(* Logix 5000 project; controller Example_PLC vendor 1 type 14 code 77 rev 19.11; software revision 19.01; part 6 of 6 *)
(* AKD_Stop_Smooth, continued *)

ROUTINE Logic   (* ladder *)
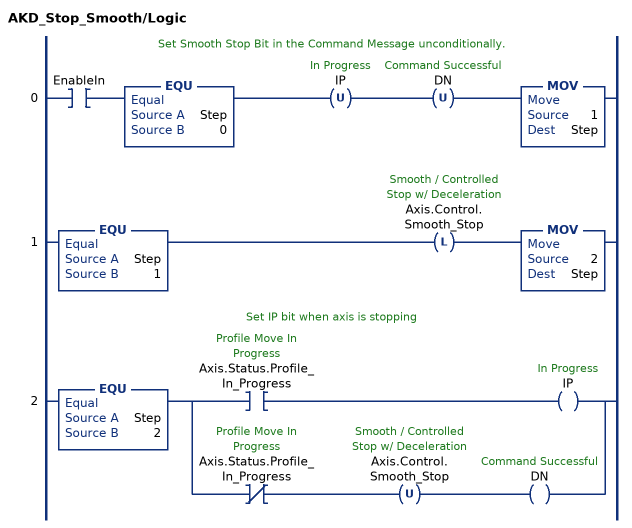
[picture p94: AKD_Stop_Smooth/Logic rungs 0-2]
   // Set Smooth Stop Bit in the Command Message unconditionally.
   0: XIC(EnableIn)EQU(Step,0)OTU(IP)OTU(DN)MOV(1,Step);
   1: EQU(Step,1)OTL(Axis.Control.Smooth_Stop)MOV(2,Step);
   // Set IP bit when axis is stopping
   2: EQU(Step,2)[XIC(Axis.Status.Profile_In_Progress) OTE(IP) ,XIO(Axis.Status.Profile_In_Progress) OTU(Axis.Control.Smooth_Stop) OTE(DN) ];
END_ROUTINE

ROUTINE Prescan   (* ladder *)
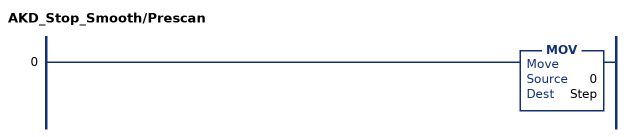
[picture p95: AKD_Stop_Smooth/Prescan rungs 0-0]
   0: MOV(0,Step);
END_ROUTINE
END_ADD_ON_INSTRUCTION

ADD_ON_INSTRUCTION AKD_Torque_Move   (* revision 2.1, ExecutePrescan, ExecuteEnableInFalse *)
// Set Torque Command
VAR_OUTPUT
   DN : BOOL; {access Read Only, visible}   // Command Successful
   ER : BOOL; {access Read Only, visible}   // Error
END_VAR
VAR_IN_OUT
   Axis : AKD_Axis; {required}
END_VAR
VAR_INPUT
   Torque : DINT; {required}   // Torque Command
END_VAR
VAR
   Response_Bytes : SINT[8];
   OS_LoadStart : BOOL;
   Command_Timeout : TIMER := (PRE := 100);   // Timeout Timer
   Command_Message_Type : SINT;   // Command Message Type
   Command_Axis_Number : SINT;   // Command Axis Number
   Response_Message_Type : SINT;   // Response Message Type
   Response_Axis_Number : SINT;   // Response Axis Number
   Command_Bytes : SINT[8];
   Step : SINT;
END_VAR

ROUTINE EnableInFalse   (* ladder *)
// EnableIn_False
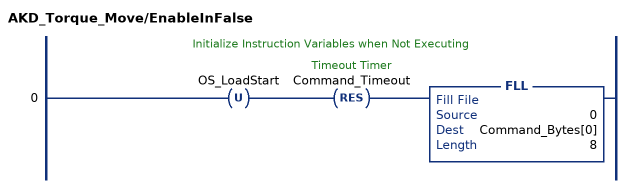
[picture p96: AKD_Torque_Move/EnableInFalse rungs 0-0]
   // Initialize Instruction Variables when Not Executing
   0: OTU(OS_LoadStart)RES(Command_Timeout)FLL(0,Command_Bytes[0],8);
END_ROUTINE

ROUTINE Logic   (* ladder *)
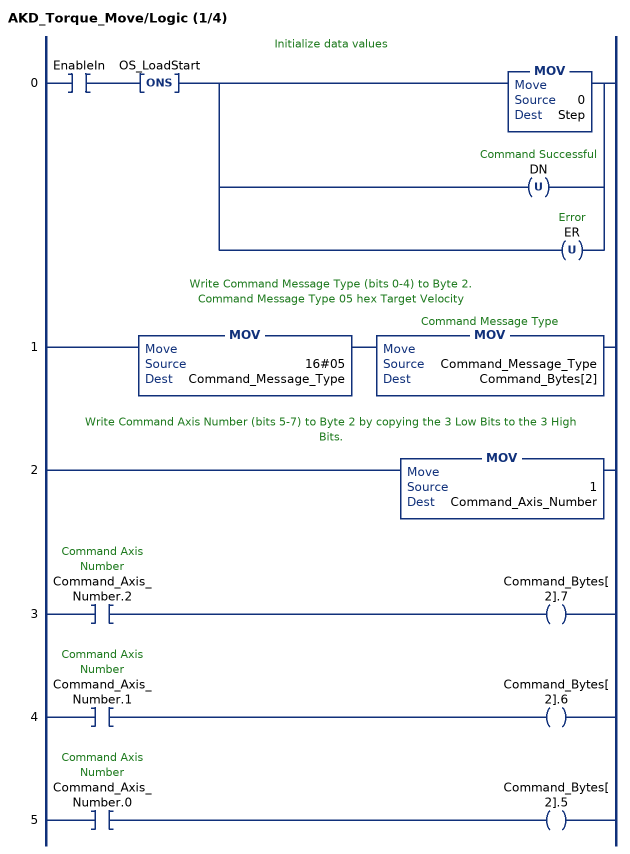
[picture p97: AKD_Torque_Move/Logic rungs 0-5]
   // Initialize data values
   0: XIC(EnableIn)ONS(OS_LoadStart)[MOV(0,Step) ,OTU(DN) ,OTU(ER) ];
   // Write Command Message Type (bits 0-4) to Byte 2.
   // Command Message Type 05 hex Target Velocity
   1: MOV(16#05,Command_Message_Type)MOV(Command_Message_Type,Command_Bytes[2]);
   // Write Command Axis Number (bits 5-7) to Byte 2 by copying the 3 Low Bits to the 3 High Bits.
   2: MOV(1,Command_Axis_Number);
   3: XIC(Command_Axis_Number.2)OTE(Command_Bytes[2].7);
   4: XIC(Command_Axis_Number.1)OTE(Command_Bytes[2].6);
   5: XIC(Command_Axis_Number.0)OTE(Command_Bytes[2].5);
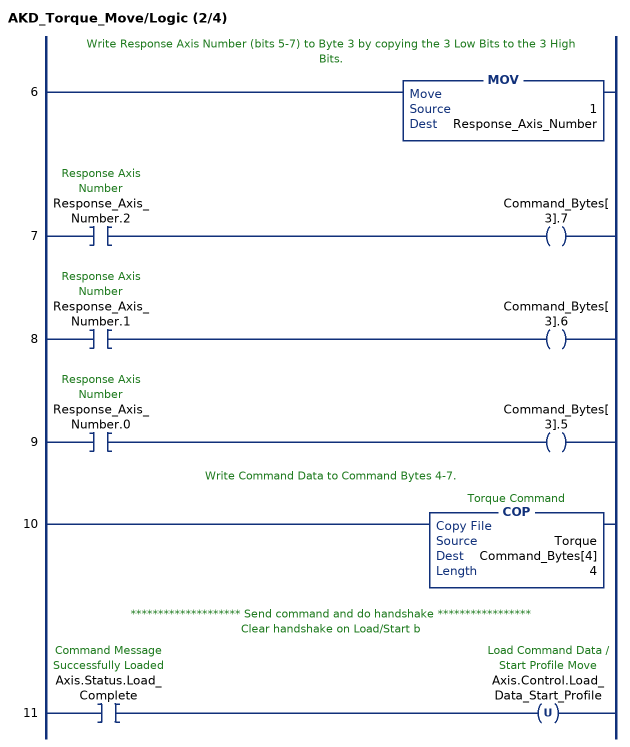
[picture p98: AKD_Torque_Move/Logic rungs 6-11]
   // Write Response Axis Number (bits 5-7) to Byte 3 by copying the 3 Low Bits to the 3 High Bits.
   6: MOV(1,Response_Axis_Number);
   7: XIC(Response_Axis_Number.2)OTE(Command_Bytes[3].7);
   8: XIC(Response_Axis_Number.1)OTE(Command_Bytes[3].6);
   9: XIC(Response_Axis_Number.0)OTE(Command_Bytes[3].5);
   // Write Command Data to Command Bytes 4-7.
   10: COP(Torque,Command_Bytes[4],4);
   // ******************** Send command and do handshake *****************
   // Clear handshake on Load/Start b
   11: XIC(Axis.Status.Load_Complete)OTU(Axis.Control.Load_Data_Start_Profile);
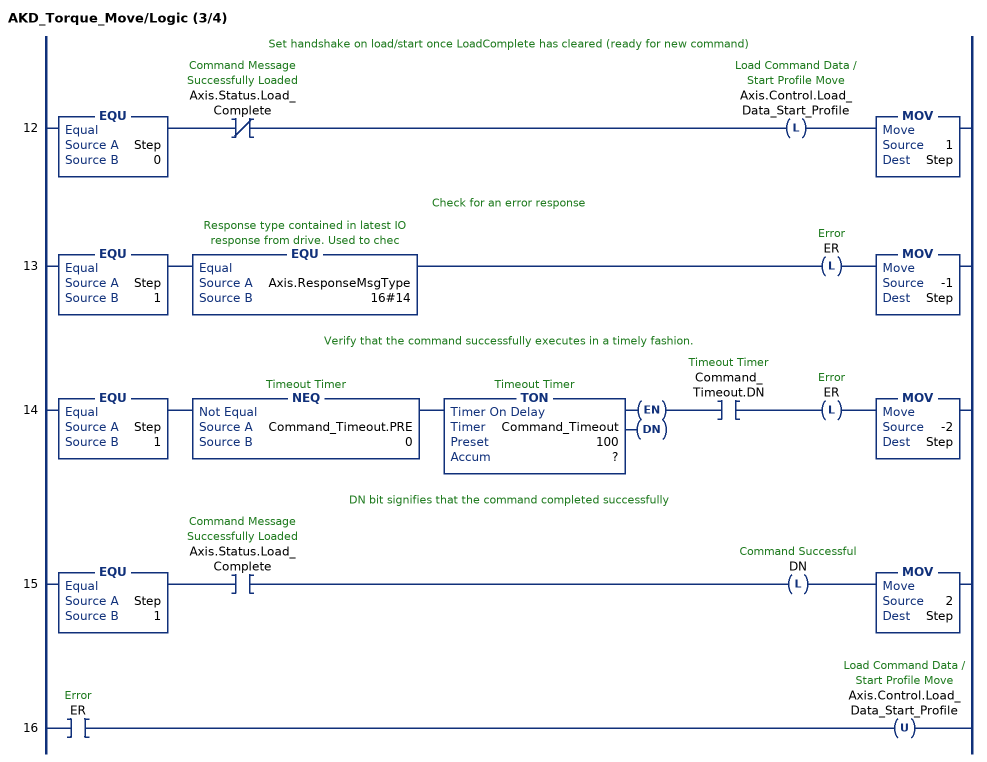
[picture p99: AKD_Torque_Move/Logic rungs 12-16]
   // Set handshake on load/start once LoadComplete has cleared (ready for new command)
   12: EQU(Step,0)XIO(Axis.Status.Load_Complete)OTL(Axis.Control.Load_Data_Start_Profile)MOV(1,Step);
   // Check for an error response
   13: EQU(Step,1)EQU(Axis.ResponseMsgType,16#14)OTL(ER)MOV(-1,Step);
   // Verify that the command successfully executes in a timely fashion.
   14: EQU(Step,1)NEQ(Command_Timeout.PRE,0)TON(Command_Timeout,?,?)XIC(Command_Timeout.DN)OTL(ER)MOV(-2,Step);
   // DN bit signifies that the command completed successfully
   15: EQU(Step,1)XIC(Axis.Status.Load_Complete)OTL(DN)MOV(2,Step);
   16: XIC(ER)OTU(Axis.Control.Load_Data_Start_Profile);
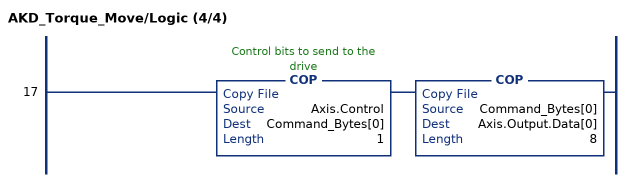
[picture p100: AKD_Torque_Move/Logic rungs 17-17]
   17: COP(Axis.Control,Command_Bytes[0],1)COP(Command_Bytes[0],Axis.Output.Data[0],8);
END_ROUTINE

ROUTINE Prescan   (* ladder *)
// Prescan
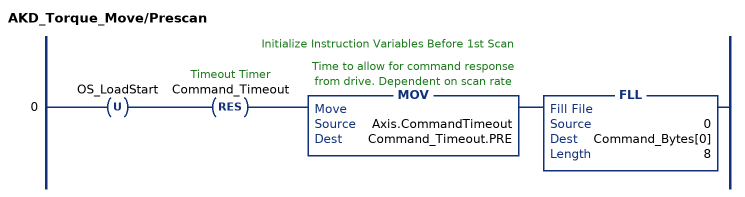
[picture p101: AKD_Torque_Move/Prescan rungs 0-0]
   // Initialize Instruction Variables Before 1st Scan
   0: OTU(OS_LoadStart)RES(Command_Timeout)MOV(Axis.CommandTimeout,Command_Timeout.PRE)FLL(0,Command_Bytes[0],8);
END_ROUTINE
END_ADD_ON_INSTRUCTION

ADD_ON_INSTRUCTION AKD_Two_Axis_Move   (* revision 1.0, ExecuteEnableInFalse *)
VAR_OUTPUT
   DN : BOOL; {visible}   // Command sent to drive
   IP : BOOL; {visible}   // Move In Process
   PC : BOOL; {visible}   // Move complete received
   ER : BOOL; {visible}   // ERROR IN MOVE
END_VAR
VAR_IN_OUT
   X_Module : AKD_Axis; {required}
   Y_Module : AKD_Axis; {required}
END_VAR
VAR_INPUT
   X_Targ_Pos : DINT; {required}   // X Axis Target Position
   Y_Targ_Pos : DINT; {required}   // Y Axis Target Position
   Linear_ACC : DINT; {required}   // Linear Motion ACC
   Linear_DEC : DINT; {required}   // Linear Motion DEC
   Linear_VEL : DINT; {required}   // Linear Velocity
   Motion_Type : DINT; {required}   // Absolute = 0, Relative = 1
END_VAR
VAR
   Int_1_sht : BOOL; {access None}
   X_Axis : AKD_Move; {access None}
   Start_Move : BOOL; {access None}
   X_1_sht : BOOL; {access None}
   Axis_1 : AKD_Axis; {access None}
   X_Move_Type : SINT; {access None}
   y_Move_Type : SINT; {access None}
   X_ACC : DINT; {access None}
   X_DEC : DINT; {access None}
   X_VEL : DINT; {access None}
   Y_1_sht : BOOL; {access None}
   Y_Axis : AKD_Move; {access None}
   Axis_2 : AKD_Axis; {access None}
   Y_ACC : DINT; {access None}
   Y_DEC : DINT; {access None}
   Y_VEL : DINT; {access None}
   Function_Step : DINT; {access None}
   Start_X_Pos : DINT; {access None}
   Start_Y_Pos : DINT; {access None}
   X_Move_Dist : DINT; {access None}
   Y_Move_Dist : REAL; {access None}
   X_Dist_SQ : REAL; {access None}
   DINT : LINT; {access None}
   Y_Dist_SQ : REAL; {access None}
   Long_X_Dist : REAL; {access None}
   Long_y_Dist : REAL; {access None}
   Total_Dist_SQ : REAL; {access None}
   Total_Dist_Slope : REAL; {access None}
   X_Multiplier : REAL; {access None}
   Y_Multiplier : REAL; {access None}
   XY_Slope : REAL; {access None}
   YX_Slope : REAL; {access None}
   Begin : BOOL; {access None}
   XY_SQ_SUM : REAL; {access None}
   XY_RMS : REAL; {access None}
   INV_XY_RMS : REAL; {access None}
   Running : BOOL; {access None}
   Time_1 : TIMER := (PRE := 50); {access None}
   Temp_Time : TIMER := (PRE := 20); {access None}
   Kick_Off_Move : BOOL; {access None}
   ONE_SCAN : BOOL; {access None}
   Delay_Pause : TIMER := (PRE := 20); {access None}
END_VAR

ROUTINE EnableInFalse   (* ladder *)
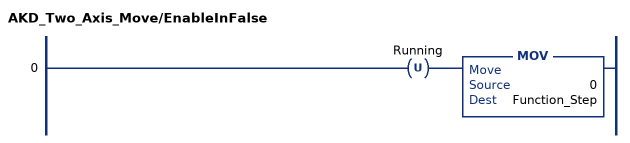
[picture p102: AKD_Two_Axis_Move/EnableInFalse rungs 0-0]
   0: OTU(Running)MOV(0,Function_Step);
END_ROUTINE

ROUTINE Logic   (* ladder *)
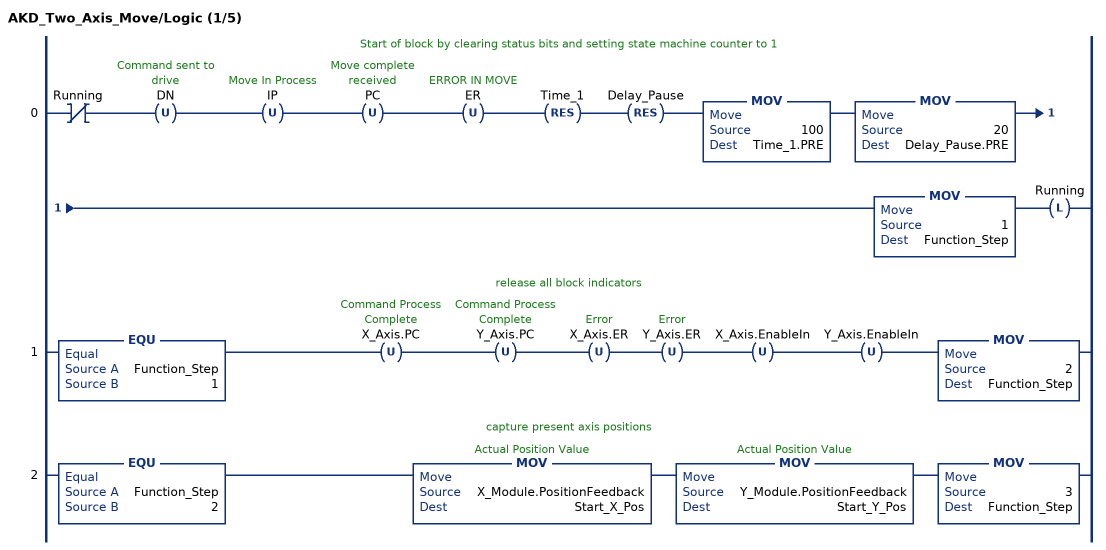
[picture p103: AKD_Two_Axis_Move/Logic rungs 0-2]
   // Start of block by clearing status bits and setting state machine counter to 1
   0: XIO(Running)OTU(DN)OTU(IP)OTU(PC)OTU(ER)RES(Time_1)RES(Delay_Pause)MOV(100,Time_1.PRE)MOV(20,Delay_Pause.PRE)MOV(1,Function_Step)OTL(Running);
   // release all block indicators
   1: EQU(Function_Step,1)OTU(X_Axis.PC)OTU(Y_Axis.PC)OTU(X_Axis.ER)OTU(Y_Axis.ER)OTU(X_Axis.EnableIn)OTU(Y_Axis.EnableIn)MOV(2,Function_Step);
   // capture present axis positions
   2: EQU(Function_Step,2)MOV(X_Module.PositionFeedback,Start_X_Pos)MOV(Y_Module.PositionFeedback,Start_Y_Pos)MOV(3,Function_Step);
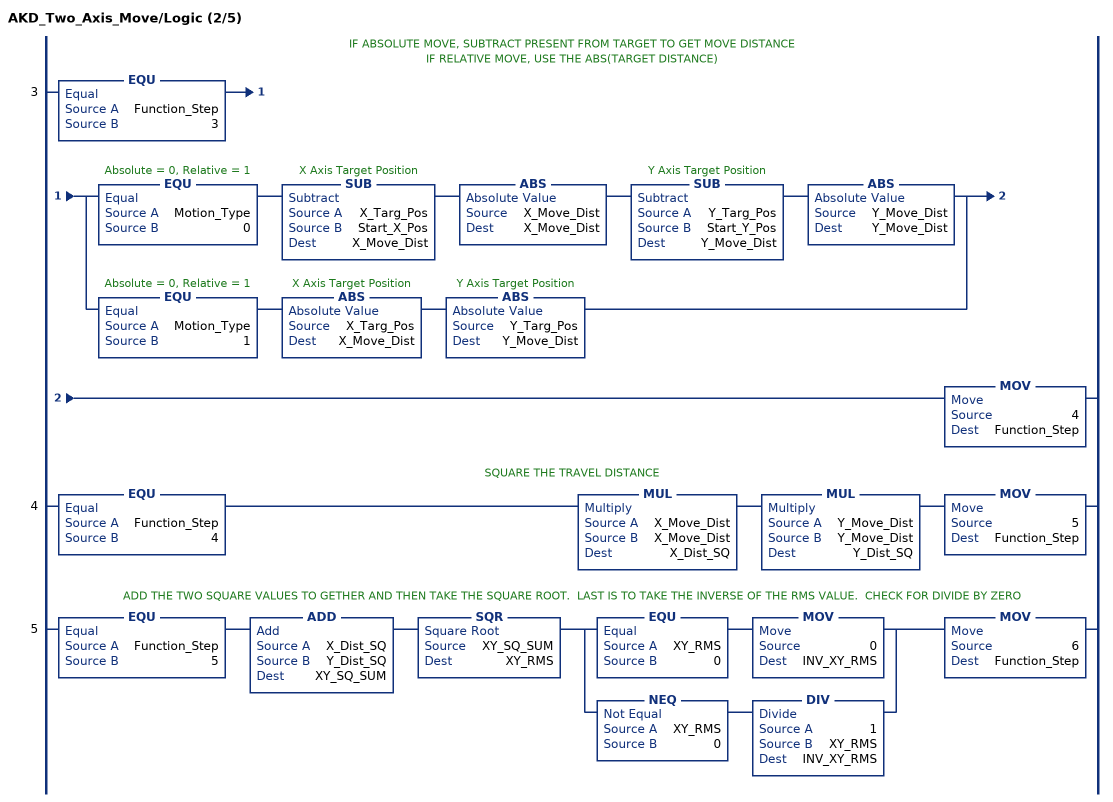
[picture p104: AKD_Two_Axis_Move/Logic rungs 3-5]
   // IF ABSOLUTE MOVE, SUBTRACT PRESENT FROM TARGET TO GET MOVE DISTANCE
   // IF RELATIVE MOVE, USE THE ABS(TARGET DISTANCE)
   3: EQU(Function_Step,3)[EQU(Motion_Type,0) SUB(X_Targ_Pos,Start_X_Pos,X_Move_Dist) ABS(X_Move_Dist,X_Move_Dist) SUB(Y_Targ_Pos,Start_Y_Pos,Y_Move_Dist) ABS(Y_Move_Dist,Y_Move_Dist) ,EQU(Motion_Type,1) ABS(X_Targ_Pos,X_Move_Dist) ABS(Y_Targ_Pos,Y_Move_Dist) ]MOV(4,Function_Step);
   // SQUARE THE TRAVEL DISTANCE
   4: EQU(Function_Step,4)MUL(X_Move_Dist,X_Move_Dist,X_Dist_SQ)MUL(Y_Move_Dist,Y_Move_Dist,Y_Dist_SQ)MOV(5,Function_Step);
   // ADD THE TWO SQUARE VALUES TO GETHER AND THEN TAKE THE SQUARE ROOT.  LAST IS TO TAKE THE INVERSE OF THE RMS VALUE.  CHECK FOR DIVIDE BY ZERO
   5: EQU(Function_Step,5)ADD(X_Dist_SQ,Y_Dist_SQ,XY_SQ_SUM)SQR(XY_SQ_SUM,XY_RMS)[EQU(XY_RMS,0) MOV(0,INV_XY_RMS) ,NEQ(XY_RMS,0) DIV(1,XY_RMS,INV_XY_RMS) ]MOV(6,Function_Step);
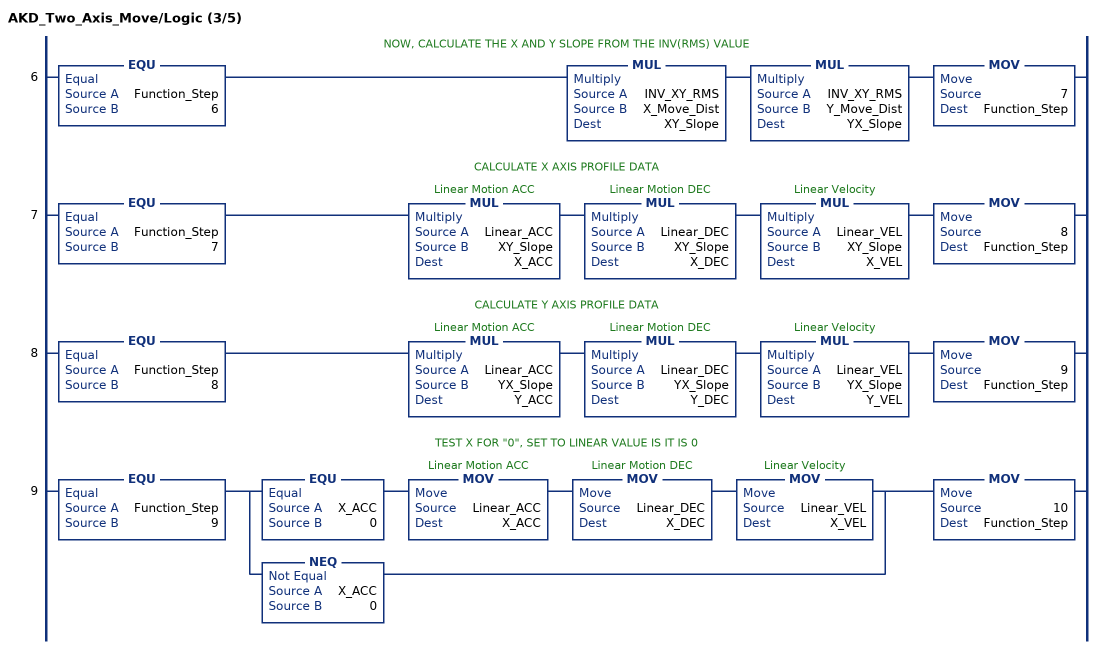
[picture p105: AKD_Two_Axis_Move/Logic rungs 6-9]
   // NOW, CALCULATE THE X AND Y SLOPE FROM THE INV(RMS) VALUE
   6: EQU(Function_Step,6)MUL(INV_XY_RMS,X_Move_Dist,XY_Slope)MUL(INV_XY_RMS,Y_Move_Dist,YX_Slope)MOV(7,Function_Step);
   // CALCULATE X AXIS PROFILE DATA
   7: EQU(Function_Step,7)MUL(Linear_ACC,XY_Slope,X_ACC)MUL(Linear_DEC,XY_Slope,X_DEC)MUL(Linear_VEL,XY_Slope,X_VEL)MOV(8,Function_Step);
   // CALCULATE Y AXIS PROFILE DATA
   8: EQU(Function_Step,8)MUL(Linear_ACC,YX_Slope,Y_ACC)MUL(Linear_DEC,YX_Slope,Y_DEC)MUL(Linear_VEL,YX_Slope,Y_VEL)MOV(9,Function_Step);
   // TEST X FOR "0", SET TO LINEAR VALUE IS IT IS 0
   9: EQU(Function_Step,9)[EQU(X_ACC,0) MOV(Linear_ACC,X_ACC) MOV(Linear_DEC,X_DEC) MOV(Linear_VEL,X_VEL) ,NEQ(X_ACC,0) ]MOV(10,Function_Step);
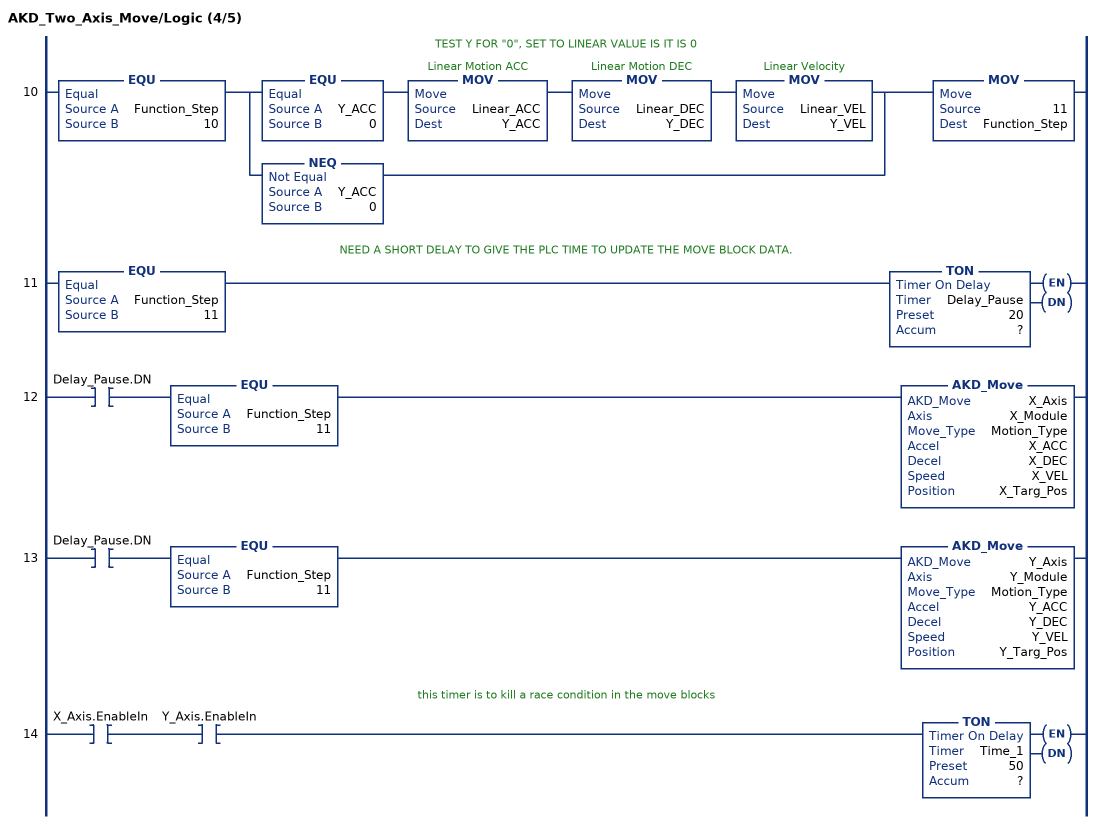
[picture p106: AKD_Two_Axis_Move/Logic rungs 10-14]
   // TEST Y FOR "0", SET TO LINEAR VALUE IS IT IS 0
   10: EQU(Function_Step,10)[EQU(Y_ACC,0) MOV(Linear_ACC,Y_ACC) MOV(Linear_DEC,Y_DEC) MOV(Linear_VEL,Y_VEL) ,NEQ(Y_ACC,0) ]MOV(11,Function_Step);
   // NEED A SHORT DELAY TO GIVE THE PLC TIME TO UPDATE THE MOVE BLOCK DATA.
   11: EQU(Function_Step,11)TON(Delay_Pause,?,?);
   12: XIC(Delay_Pause.DN)EQU(Function_Step,11)AKD_Move(X_Axis,X_Module,Motion_Type,X_ACC,X_DEC,X_VEL,X_Targ_Pos);
   13: XIC(Delay_Pause.DN)EQU(Function_Step,11)AKD_Move(Y_Axis,Y_Module,Motion_Type,Y_ACC,Y_DEC,Y_VEL,Y_Targ_Pos);
   // this timer is to kill a race condition in the move blocks
   14: XIC(X_Axis.EnableIn)XIC(Y_Axis.EnableIn)TON(Time_1,?,?);
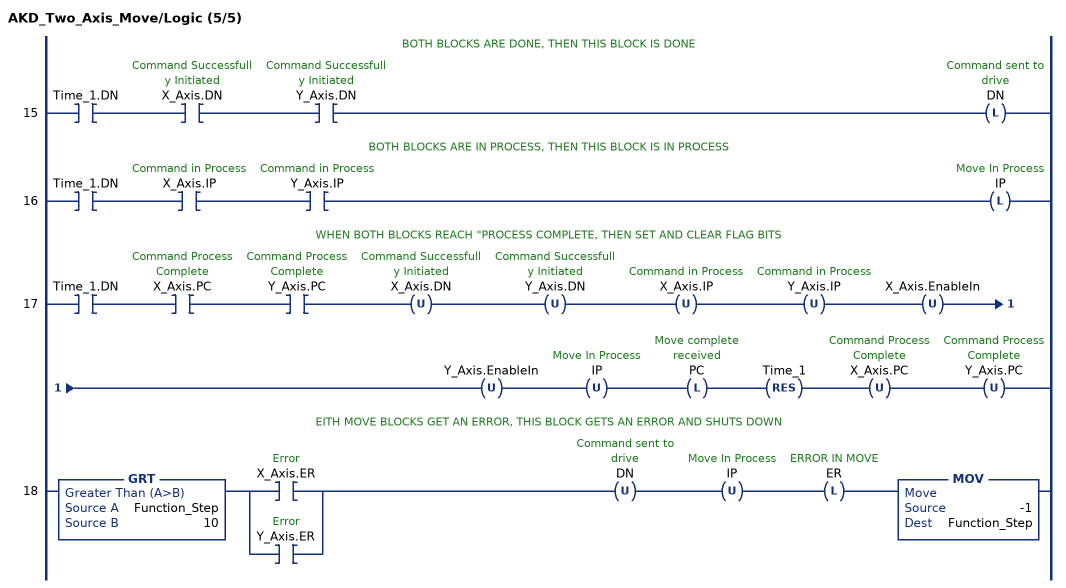
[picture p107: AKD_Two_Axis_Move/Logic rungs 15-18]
   // BOTH BLOCKS ARE DONE, THEN THIS BLOCK IS DONE
   15: XIC(Time_1.DN)XIC(X_Axis.DN)XIC(Y_Axis.DN)OTL(DN);
   // BOTH BLOCKS ARE IN PROCESS, THEN THIS BLOCK IS IN PROCESS
   16: XIC(Time_1.DN)XIC(X_Axis.IP)XIC(Y_Axis.IP)OTL(IP);
   // WHEN BOTH BLOCKS REACH "PROCESS COMPLETE, THEN SET AND CLEAR FLAG BITS
   17: XIC(Time_1.DN)XIC(X_Axis.PC)XIC(Y_Axis.PC)OTU(X_Axis.DN)OTU(Y_Axis.DN)OTU(X_Axis.IP)OTU(Y_Axis.IP)OTU(X_Axis.EnableIn)OTU(Y_Axis.EnableIn)OTU(IP)OTL(PC)RES(Time_1)OTU(X_Axis.PC)OTU(Y_Axis.PC);
   // EITH MOVE BLOCKS GET AN ERROR, THIS BLOCK GETS AN ERROR AND SHUTS DOWN
   18: GRT(Function_Step,10)[XIC(X_Axis.ER) ,XIC(Y_Axis.ER) ]OTU(DN)OTU(IP)OTL(ER)MOV(-1,Function_Step);
END_ROUTINE

ROUTINE Prescan   (* ladder *)
END_ROUTINE
END_ADD_ON_INSTRUCTION

VAR_GLOBAL   (* controller tags *)
   AKD_1 : AKD_Drive;
   AKD_2 : AKD_Drive;
   Axis_1 : AKD_Drive;
   Axis_1_Dis : AKD_Disable;
   Axis_1_EN : AKD_Enable := (DN := 1);
   Axis_1_HOME : AKD_Home := (DN := 1, PC := 1, TimeOut_mS := 5000);
   Axis_1_Move : AKD_Move := (Move_Type := 1, Accel := 10922666, Decel := 10922666, Speed := 65536, Position := 65536);
   Axis_2_Dis : AKD_Disable;
   Axis_2_EN : AKD_Enable;
   Axis_2_HOME : AKD_Home;
   Axis_2_Move : AKD_Move;
   Axis_Is_Moving : BOOL;
   AXIS_ONE : AKD_Axis := (Control.Enable := 1, Status.Home_Level := 1, Status.Enable := 1, Input.Data[0] := -96, Input.Data[3] := 32, Input.Data[8] := -112, Input.Data[9] := 82, Input.Data[10] := -32, Input.Data[11] := -1, Input.Data[12] := -81, Input.Data[13] := -1, Input.Data[14] := -1, Input.Data[15] := -1, Input.Data[16] := 6, Output.Data[0] := -128, Output.Data[2] := 39, Output.Data[3] := 32, Output.Data[14] := 1, Output.Data[16] := -86, Output.Data[17] := -86, Output.Data[18] := -90, Output.Data[20] := -86, Output.Data[21] := -86, Output.Data[22] := -90, Output.Data[24] := 1, PositionFeedback := -2076016, VelocityFeedback := -81);
   Axis_Two : AKD_Axis;
   B_DRV_ACTIVE : AKD_Get_Parameter;
   BLK_DRV_DISSOURCE : AKD_Get_Parameter := (Parameter_Number := 121);
   BLK_DRV_MOTIONSTAT : AKD_Get_Parameter := (Parameter_Number := 135);
   BLK_FAULT_RESET : AKD_Fault_Reset := (DN := 1);
   BLK_GET_FAULT1 : AKD_Get_Parameter := (DN := 1, Parameter_Number := 478);
   BLK_GET_FAULT10 : AKD_Get_Parameter := (DN := 1, Parameter_Number := 487);
   BLK_GET_FAULT2 : AKD_Get_Parameter := (DN := 1, Parameter_Number := 479);
   BLK_GET_FAULT3 : AKD_Get_Parameter := (DN := 1, Parameter_Number := 480);
   BLK_GET_FAULT4 : AKD_Get_Parameter := (DN := 1, Parameter_Number := 481);
   BLK_GET_FAULT5 : AKD_Get_Parameter := (DN := 1, Parameter_Number := 482);
   BLK_GET_FAULT6 : AKD_Get_Parameter := (DN := 1, Parameter_Number := 483);
   BLK_GET_FAULT7 : AKD_Get_Parameter := (DN := 1, Parameter_Number := 484);
   BLK_GET_FAULT8 : AKD_Get_Parameter := (DN := 1, Parameter_Number := 485);
   BLK_GET_FAULT9 : AKD_Get_Parameter := (DN := 1, Parameter_Number := 486);
   BLK_JOG : AKD_Jog := (Accel := 10922666, Decel := 10922666, Speed := 65536, DN := 1);
   BLK_JOG_REV : AKD_Jog;
   BLK_Reset : AKD_Shutdown_Reset;
   BLK_ShutDown : AKD_Shutdown := (DN := 1);
   BLK_STOP : AKD_Stop_Smooth := (DN := 1);
   CLRFAULT_1_SHOT : BOOL;
   Cord_Move_1 : AKD_Two_Axis_Move;
   DATA_DRV_DISSOURCE : DINT;
   DATA_DRV_MOTIONSTAT : DINT;
   DISABLE : BOOL;
   DISABLE_1_SHOT : BOOL;
   DISABLE_2_SHOT : BOOL;
   DISSOURCE_1_SHOT : BOOL;
   Dummy : BOOL;
   ENABLE : BOOL;
   ENABLE_1_SHOT : BOOL;
   ENABLE_2_SHOT : BOOL;
   FAULT_1 : DINT;
   FAULT_10 : DINT;
   FAULT_2 : DINT;
   FAULT_3 : DINT;
   FAULT_4 : DINT;
   FAULT_5 : DINT;
   FAULT_6 : DINT;
   FAULT_7 : DINT;
   FAULT_8 : DINT;
   FAULT_9 : DINT;
   FAULT_FIRST_STEP : BOOL;
   from : BOOL;
   GET_FAULT_BUSY : BOOL;
   GET_FAULT_COUNTER : DINT;
   GETFAULT_1_SHOT : BOOL;
   HOME_1_SHOT : BOOL;
   HOME_2_SHOT : BOOL;
   Is_Axis_Enabled : BOOL := 1;
   Is_Axis_Faulted : BOOL;
   Is_Axis_Homed : BOOL := 1;
   Is_Axis_In_Position : BOOL;
   JOG_1_SHOT : BOOL;
   JOG_2_SHOT : BOOL;
   JOG_AXIS_1 : BOOL;
   JOG_AXIS_FWD : BOOL;
   JOG_AXIS_REV : BOOL;
   MOTIONSTAT_1_SHOT : BOOL;
   MOVE_1_SHOT : BOOL;
   MOVE_2_SHOT : BOOL;
   MOVE_CORD_SHOT : BOOL;
   Position : DINT;
   Reset_1_Shot : BOOL;
   Reset_Shutdown : BOOL;
   shutdown : BOOL;
   ShutDown_1_Shot : BOOL;
   START_CORD_MOVE : BOOL;
   START_DRV_CLRFAULTS : BOOL;
   START_DRV_DISSOURCE : BOOL;
   START_DRV_MOTIONSTAT : BOOL;
   START_GET_FAULTS : BOOL;
   START_HOME_MOVE : BOOL;
   Start_Shut_Down : BOOL;
   START_X_MOVE : BOOL;
   START_Y_MOVE : BOOL;
   STOP_1_STOP : BOOL := 1;
   Test1 : BOOL;
END_VAR

PROGRAM MainProgram   (* main routine MainRoutine *)

ROUTINE MainRoutine   (* ladder *)
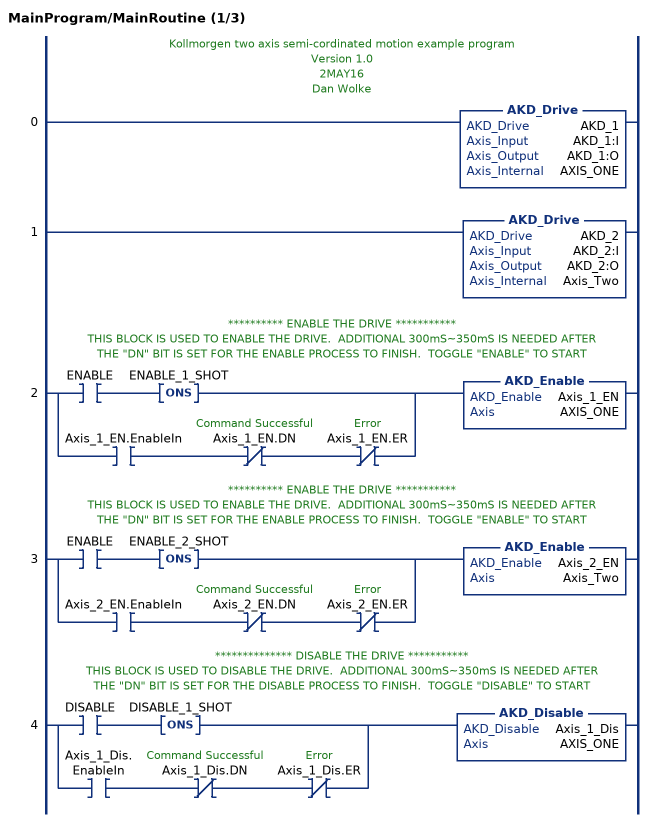
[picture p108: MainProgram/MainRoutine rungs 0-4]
   // Kollmorgen two axis semi-cordinated motion example program
   // Version 1.0
   // 2MAY16
   // Dan Wolke
   0: AKD_Drive(AKD_1,AKD_1:I,AKD_1:O,AXIS_ONE);
   1: AKD_Drive(AKD_2,AKD_2:I,AKD_2:O,Axis_Two);
   // ********** ENABLE THE DRIVE ***********
   // THIS BLOCK IS USED TO ENABLE THE DRIVE.  ADDITIONAL 300mS~350mS IS NEEDED AFTER THE "DN" BIT IS SET FOR THE ENABLE PROCESS TO FINISH.  TOGGLE "ENABLE" TO START
   2: [XIC(ENABLE) ONS(ENABLE_1_SHOT) ,XIC(Axis_1_EN.EnableIn) XIO(Axis_1_EN.DN) XIO(Axis_1_EN.ER) ]AKD_Enable(Axis_1_EN,AXIS_ONE);
   // ********** ENABLE THE DRIVE ***********
   // THIS BLOCK IS USED TO ENABLE THE DRIVE.  ADDITIONAL 300mS~350mS IS NEEDED AFTER THE "DN" BIT IS SET FOR THE ENABLE PROCESS TO FINISH.  TOGGLE "ENABLE" TO START
   3: [XIC(ENABLE) ONS(ENABLE_2_SHOT) ,XIC(Axis_2_EN.EnableIn) XIO(Axis_2_EN.DN) XIO(Axis_2_EN.ER) ]AKD_Enable(Axis_2_EN,Axis_Two);
   // ************** DISABLE THE DRIVE ***********
   // THIS BLOCK IS USED TO DISABLE THE DRIVE.  ADDITIONAL 300mS~350mS IS NEEDED AFTER THE "DN" BIT IS SET FOR THE DISABLE PROCESS TO FINISH.  TOGGLE "DISABLE" TO START
   4: [XIC(DISABLE) ONS(DISABLE_1_SHOT) ,XIC(Axis_1_Dis.EnableIn) XIO(Axis_1_Dis.DN) XIO(Axis_1_Dis.ER) ]AKD_Disable(Axis_1_Dis,AXIS_ONE);
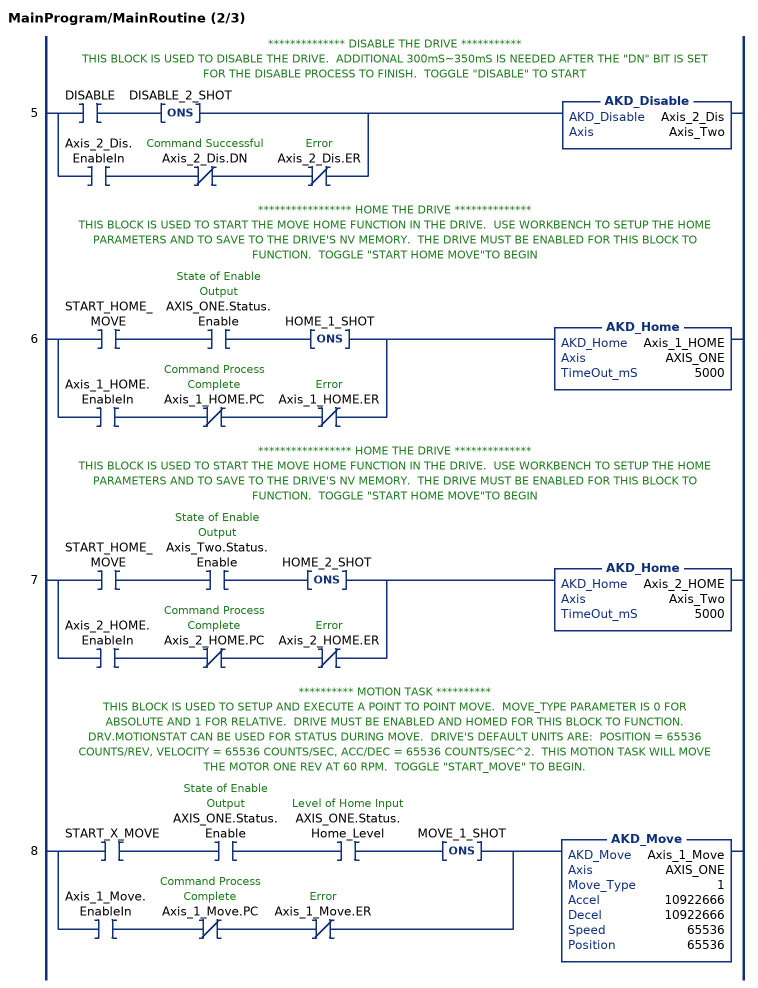
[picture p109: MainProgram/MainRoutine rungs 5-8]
   // ************** DISABLE THE DRIVE ***********
   // THIS BLOCK IS USED TO DISABLE THE DRIVE.  ADDITIONAL 300mS~350mS IS NEEDED AFTER THE "DN" BIT IS SET FOR THE DISABLE PROCESS TO FINISH.  TOGGLE "DISABLE" TO START
   5: [XIC(DISABLE) ONS(DISABLE_2_SHOT) ,XIC(Axis_2_Dis.EnableIn) XIO(Axis_2_Dis.DN) XIO(Axis_2_Dis.ER) ]AKD_Disable(Axis_2_Dis,Axis_Two);
   // ***************** HOME THE DRIVE **************
   // THIS BLOCK IS USED TO START THE MOVE HOME FUNCTION IN THE DRIVE.  USE WORKBENCH TO SETUP THE HOME PARAMETERS AND TO SAVE TO THE DRIVE'S NV MEMORY.  THE DRIVE MUST BE ENABLED FOR THIS BLOCK TO FUNCTION.  TOGGLE "START HOME MOVE"TO BEGIN
   6: [XIC(START_HOME_MOVE) XIC(AXIS_ONE.Status.Enable) ONS(HOME_1_SHOT) ,XIC(Axis_1_HOME.EnableIn) XIO(Axis_1_HOME.PC) XIO(Axis_1_HOME.ER) ]AKD_Home(Axis_1_HOME,AXIS_ONE,5000);
   // ***************** HOME THE DRIVE **************
   // THIS BLOCK IS USED TO START THE MOVE HOME FUNCTION IN THE DRIVE.  USE WORKBENCH TO SETUP THE HOME PARAMETERS AND TO SAVE TO THE DRIVE'S NV MEMORY.  THE DRIVE MUST BE ENABLED FOR THIS BLOCK TO FUNCTION.  TOGGLE "START HOME MOVE"TO BEGIN
   7: [XIC(START_HOME_MOVE) XIC(Axis_Two.Status.Enable) ONS(HOME_2_SHOT) ,XIC(Axis_2_HOME.EnableIn) XIO(Axis_2_HOME.PC) XIO(Axis_2_HOME.ER) ]AKD_Home(Axis_2_HOME,Axis_Two,5000);
   // ********** MOTION TASK **********
   // THIS BLOCK IS USED TO SETUP AND EXECUTE A POINT TO POINT MOVE.  MOVE_TYPE PARAMETER IS 0 FOR ABSOLUTE AND 1 FOR RELATIVE.  DRIVE MUST BE ENABLED AND HOMED FOR THIS BLOCK TO FUNCTION.  DRV.MOTIONSTAT CAN BE USED FOR STATUS DURING MOVE.  DRIVE'S DEFAULT UNITS ARE:  POSITION = 65536 COUNTS/REV, VELOCITY = 65536 COUNTS/SEC, ACC/DEC = 65536 COUNTS/SEC^2.  THIS MOTION TASK WILL MOVE THE MOTOR ONE REV AT 60 RPM.  TOGGLE "START_MOVE" TO BEGIN.
   8: [XIC(START_X_MOVE) XIC(AXIS_ONE.Status.Enable) XIC(AXIS_ONE.Status.Home_Level) ONS(MOVE_1_SHOT) ,XIC(Axis_1_Move.EnableIn) XIO(Axis_1_Move.PC) XIO(Axis_1_Move.ER) ]AKD_Move(Axis_1_Move,AXIS_ONE,1,10922666,10922666,65536,65536);
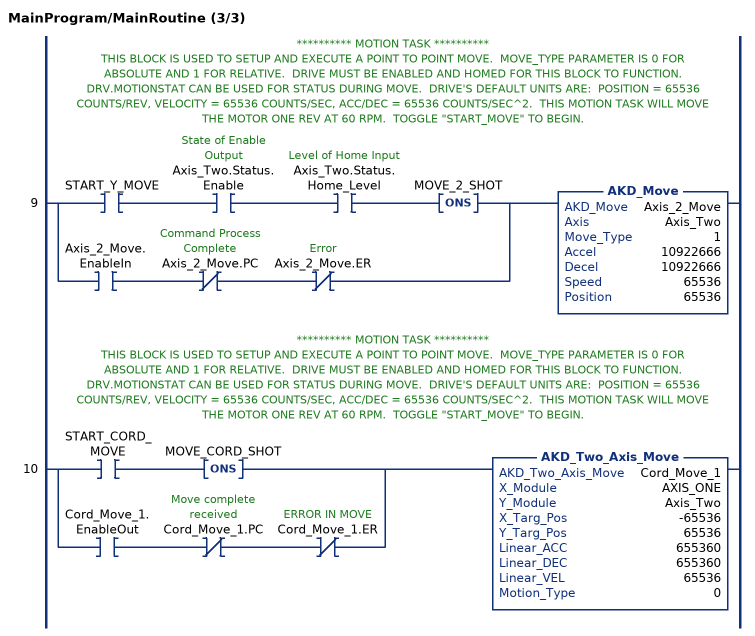
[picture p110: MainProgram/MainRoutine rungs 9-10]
   // ********** MOTION TASK **********
   // THIS BLOCK IS USED TO SETUP AND EXECUTE A POINT TO POINT MOVE.  MOVE_TYPE PARAMETER IS 0 FOR ABSOLUTE AND 1 FOR RELATIVE.  DRIVE MUST BE ENABLED AND HOMED FOR THIS BLOCK TO FUNCTION.  DRV.MOTIONSTAT CAN BE USED FOR STATUS DURING MOVE.  DRIVE'S DEFAULT UNITS ARE:  POSITION = 65536 COUNTS/REV, VELOCITY = 65536 COUNTS/SEC, ACC/DEC = 65536 COUNTS/SEC^2.  THIS MOTION TASK WILL MOVE THE MOTOR ONE REV AT 60 RPM.  TOGGLE "START_MOVE" TO BEGIN.
   9: [XIC(START_Y_MOVE) XIC(Axis_Two.Status.Enable) XIC(Axis_Two.Status.Home_Level) ONS(MOVE_2_SHOT) ,XIC(Axis_2_Move.EnableIn) XIO(Axis_2_Move.PC) XIO(Axis_2_Move.ER) ]AKD_Move(Axis_2_Move,Axis_Two,1,10922666,10922666,65536,65536);
   // ********** MOTION TASK **********
   // THIS BLOCK IS USED TO SETUP AND EXECUTE A POINT TO POINT MOVE.  MOVE_TYPE PARAMETER IS 0 FOR ABSOLUTE AND 1 FOR RELATIVE.  DRIVE MUST BE ENABLED AND HOMED FOR THIS BLOCK TO FUNCTION.  DRV.MOTIONSTAT CAN BE USED FOR STATUS DURING MOVE.  DRIVE'S DEFAULT UNITS ARE:  POSITION = 65536 COUNTS/REV, VELOCITY = 65536 COUNTS/SEC, ACC/DEC = 65536 COUNTS/SEC^2.  THIS MOTION TASK WILL MOVE THE MOTOR ONE REV AT 60 RPM.  TOGGLE "START_MOVE" TO BEGIN.
   10: [XIC(START_CORD_MOVE) ONS(MOVE_CORD_SHOT) ,XIC(Cord_Move_1.EnableOut) XIO(Cord_Move_1.PC) XIO(Cord_Move_1.ER) ]AKD_Two_Axis_Move(Cord_Move_1,AXIS_ONE,Axis_Two,-65536,65536,655360,655360,65536,0);
END_ROUTINE
END_PROGRAM
